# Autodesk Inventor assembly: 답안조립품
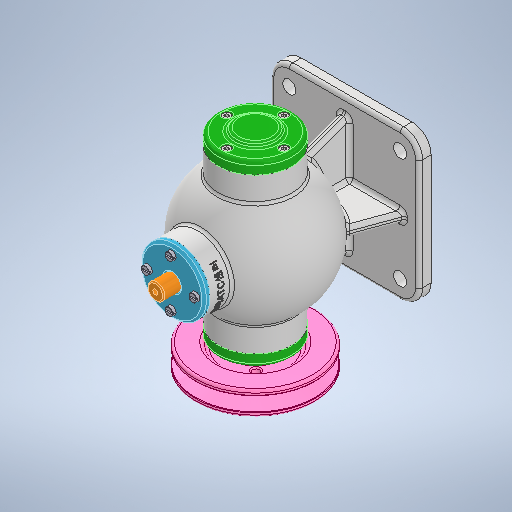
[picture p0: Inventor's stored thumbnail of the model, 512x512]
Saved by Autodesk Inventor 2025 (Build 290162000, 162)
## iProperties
Created: 2025-08
Part Number: 답안조립품
Document SubType Name: Assembly
Designer: infra028
Author: infra028
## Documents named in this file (15)
- C:\Users\infra028\Desktop\750807V1008\답안조립품.iam
- C:\Users\infra028\Desktop\750807V1008\본체.ipt
- C:\Users\infra028\Desktop\750807V1008\뒤커버\뒤커버.ipt
- C:\Users\infra028\Desktop\750807V1008\앞커버\앞커버.ipt
- C:\Users\infra028\Desktop\750807V1008\볼트 M4 x 16\볼트 M4 x 16.ipt
- C:\Users\infra028\Desktop\750807V1008\편심축\편심축.ipt
- C:\Users\infra028\Desktop\750807V1008\키 4 x 4 x 12\키 4 x 4 x 12.ipt
- C:\Users\infra028\Desktop\750807V1008\오일실 15 30 7\오일실 15 30 7.ipt
- C:\Users\infra028\Desktop\750807V1008\V-벨트풀리\V-벨트풀리.ipt
- C:\Users\infra028\Desktop\750807V1008\너트 M8\너트 M8.ipt
- C:\Users\infra028\Desktop\750807V1008\칼라\칼라.ipt
- C:\Users\infra028\Desktop\750807V1008\베어링- 6202\베어링- 6202.ipt
- C:\Users\infra028\Desktop\750807V1008\상부커버\상부커버.ipt
- C:\Users\infra028\Desktop\750807V1008\볼트 M4 x 12\볼트 M4 x 12.ipt
- C:\Users\infra028\Desktop\750807V1008\슬라이드\슬라이드.ipt
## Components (1 placed, 1 different names)
1. V-벨트풀리:1
